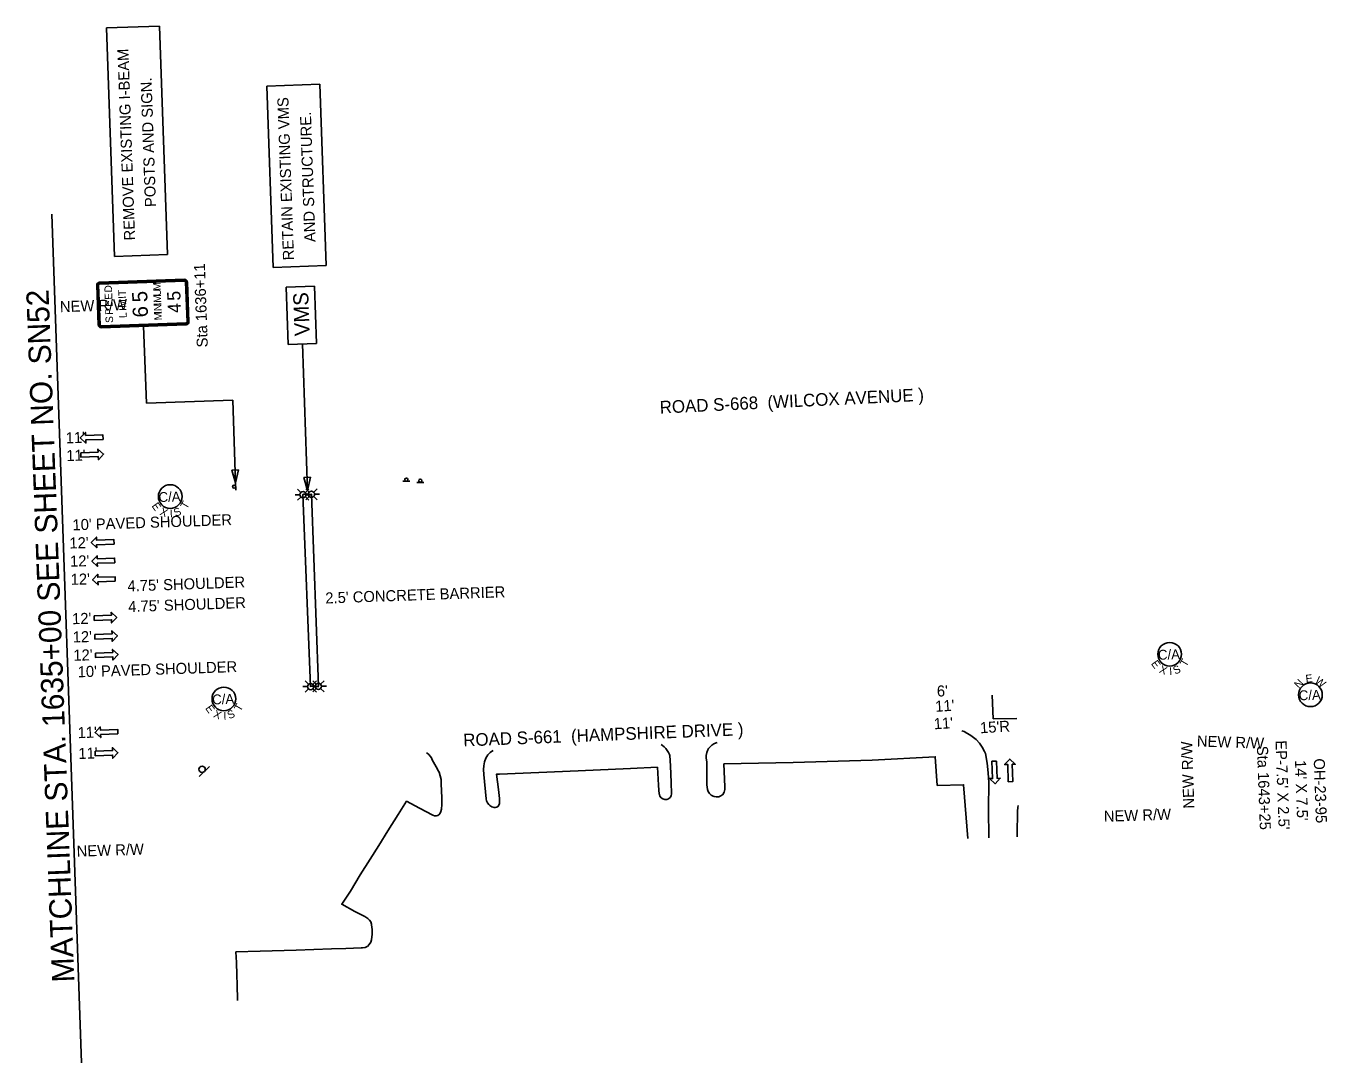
# Model space of a CAD drawing. Extents: x 1810445 to 1812085, y 1189733 to 1190648.
# Drawn here: x 1810445 to 1811270, y 1189817 to 1190475 of the extents above; entities that cross this region are included whole.
import ezdxf

# ---------------------------------------------------------------- set-up
doc = ezdxf.new("R2010")
doc.units = 0
for name, color, linetype in [('RD_EX_Misc', 7, 'Continuous'), ('RD_EX_Road', 7, 'Continuous'), ('RD_EX_UT', 7, 'Continuous'), ('RD_PD_Final_LnLine', 7, 'Continuous'), ('RD_PD_Final_TX', 7, 'Continuous'), ('RD_PD_RW_TX', 7, 'Continuous'), ('RD_SHT_MatchLine', 7, 'Continuous'), ('RD_SHT_TX', 7, 'Continuous'), ('RD_Sketch10', 7, 'Continuous'), ('RD_Sketch8', 7, 'Continuous'), ('RD_TX_RoadID', 7, 'Continuous'), ('SN_P_Signs', 7, 'Continuous')]:
    doc.layers.add(name, color=color, linetype=linetype)

# ---------------------------------------------------------------- blocks, each defined once
blk = doc.blocks.new('SARRW2')
at = {"layer": 'RD_PD_Final_LnLine'}
blk.add_lwpolyline([(-12, 1.2), (-12, -1.2), (-2.83, -1.2), (-2.83, -2.83), (0, 0), (-2.83, 2.83), (-2.83, 1.2)], close=True, dxfattribs=at)

msp = doc.modelspace()

# ---------------------------------------------------------------- linework, layer by layer
at = {"layer": 'RD_EX_Misc'}
msp.add_lwpolyline([(1810630.31, 1190056.09), (1810625.32, 1190055.92), (1810620.5, 1190177.71), (1810625.98, 1190177.88), (1810630.31, 1190056.09)], dxfattribs=at)
at = {"layer": 'RD_EX_Road'}
for points in [[(1811041.97, 1189959.43), (1811039.33, 1189993.58), (1811022.7, 1189993.16), (1811021.41, 1190011.32), (1810981.35, 1190009.17), (1810931.36, 1190007.76), (1810887.46, 1190006.81), (1810888.06, 1189992.18), (1810888.03, 1189990.52), (1810887.6, 1189988.91), (1810886.82, 1189987.44), (1810886.77, 1189987.37), (1810885.54, 1189986.52), (1810884.13, 1189986.01), (1810882.63, 1189985.88), (1810881.16, 1189986.15), (1810880.65, 1189986.34), (1810879.35, 1189986.99), (1810878.27, 1189987.97), (1810877.48, 1189989.2), (1810877.06, 1189990.6), (1810877.05, 1189990.64), (1810876.69, 1189993.44), (1810876.57, 1189999.43), (1810876.59, 1190006.08), (1810876.54, 1190008.14), (1810876.19, 1190010.35), (1810876.2, 1190012.2), (1810876.51, 1190014.06), (1810877.2, 1190015.81), (1810877.62, 1190016.53), (1810878.64, 1190017.65), (1810879.8, 1190018.63), (1810881.08, 1190019.45), (1810882.45, 1190020.1), (1810883.07, 1190020.29)], [(1811038.3, 1190027.77), (1811039.65, 1190027.28), (1811041.53, 1190026.38), (1811043.33, 1190025.31), (1811044.85, 1190024.21), (1811047.24, 1190022.24), (1811049.36, 1190019.99), (1811051.18, 1190017.48), (1811052.66, 1190014.76), (1811053.21, 1190013.49), (1811054.3, 1190007.31), (1811055, 1190001.07), (1811055.3, 1189995.02), (1811055.25, 1189978), (1811055.29, 1189959.9)], [(1810698.93, 1190013.8), (1810699.22, 1190013.63), (1810700.27, 1190012.75), (1810701.19, 1190011.74), (1810701.95, 1190010.6), (1810702.54, 1190009.36), (1810705.05, 1190004.91), (1810706.52, 1190002.15), (1810706.8, 1190001.55), (1810707.63, 1189999.22), (1810708.08, 1189996.8), (1810708.16, 1189993.31), (1810708.35, 1189990.47), (1810708.52, 1189984.36), (1810708.49, 1189981.12), (1810708.42, 1189978.17), (1810708.04, 1189976.59), (1810707.3, 1189975.15), (1810707.09, 1189974.85), (1810706.16, 1189974.16), (1810705.05, 1189973.81), (1810703.9, 1189973.85), (1810702.9, 1189974.23), (1810694.4, 1189978.82), (1810686.21, 1189983.15), (1810680.86, 1189974.72), (1810674.44, 1189964.28), (1810668.58, 1189955.14), (1810663.1, 1189946.34), (1810656.87, 1189936.47), (1810650.75, 1189926.07), (1810645.13, 1189917.74), (1810653.54, 1189913.25), (1810659.69, 1189909.93), (1810661.58, 1189908.72), (1810662.69, 1189907.77), (1810663.5, 1189906.56), (1810663.96, 1189905.17), (1810664.02, 1189904.82), (1810664.41, 1189901.68), (1810664.42, 1189898.51), (1810664.03, 1189895.36), (1810664.01, 1189895.3), (1810663.48, 1189893.69), (1810662.6, 1189892.25), (1810661.4, 1189891.05), (1810661.31, 1189890.98), (1810659.9, 1189890.35), (1810658.38, 1189890.1), (1810657.51, 1189890.13), (1810647.81, 1189889.77), (1810638.63, 1189889.42), (1810616.26, 1189888.58), (1810593.41, 1189887.93), (1810578.07, 1189887.51), (1810578.47, 1189880.93), (1810578.54, 1189872.9), (1810578.78, 1189866.75), (1810579.13, 1189857.1), (1810579.15, 1189856.63)], [(1810845.42, 1190004.73), (1810828.28, 1190003.91), (1810794.99, 1190002.48), (1810745.05, 1190000.29), (1810743.22, 1190000.2), (1810744.45, 1189990.48), (1810745.09, 1189984.93), (1810745.25, 1189982.83), (1810745.2, 1189981.65), (1810744.77, 1189980.54), (1810744.31, 1189979.93), (1810743.46, 1189979.34), (1810742.45, 1189979.1), (1810741.72, 1189979.17), (1810740.29, 1189979.66), (1810739.03, 1189980.5), (1810738.4, 1189981.14), (1810737.51, 1189982.19), (1810736.94, 1189983.46), (1810736.76, 1189984.55), (1810735.32, 1190000.01), (1810735.1, 1190003.19), (1810735.19, 1190005.64), (1810735.67, 1190008.05), (1810736.53, 1190010.35), (1810737.75, 1190012.49), (1810737.99, 1190012.84), (1810739.21, 1190014.12), (1810740.68, 1190015.1), (1810741.18, 1190015.29)], [(1810847.56, 1190019.04), (1810848.4, 1190018.56), (1810849.58, 1190017.65), (1810850.63, 1190016.59), (1810851.53, 1190015.4), (1810852.27, 1190014.1), (1810852.84, 1190012.72), (1810853.03, 1190012.06), (1810853.48, 1190005.56), (1810854, 1189995.09), (1810854.28, 1189987.73), (1810853.96, 1189986.53), (1810853.28, 1189985.49), (1810852.31, 1189984.71), (1810851.14, 1189984.28), (1810849.9, 1189984.22), (1810848.7, 1189984.56), (1810847.67, 1189985.25), (1810846.9, 1189986.23), (1810846.48, 1189987.4), (1810846.42, 1189987.79), (1810846.23, 1189990.06), (1810845.96, 1189993.27), (1810845.42, 1190004.73)], [(1811074.05, 1189980.37), (1811073.74, 1189979.19), (1811073.52, 1189976.75), (1811073.54, 1189975.74), (1811073.41, 1189963.08), (1811073.41, 1189960.54)]]:
    msp.add_lwpolyline(points, dxfattribs=at)
at = {"layer": 'RD_EX_UT'}
for p, q in [((1810618.63, 1190177.55), (1810615.7, 1190177.55)), ((1810617.17, 1190181.09), (1810619.26, 1190178.99)), ((1810623.92, 1190177.82), (1810620.99, 1190177.82)), ((1810622.08, 1190178.92), (1810624.24, 1190181.09)), ((1810622.46, 1190181.36), (1810624.55, 1190179.26)), ((1810622.46, 1190174.28), (1810624.54, 1190176.36)), ((1810625.7, 1190177.55), (1810622.63, 1190177.55)), ((1810627.37, 1190179.19), (1810629.53, 1190181.36)), ((1810627.38, 1190176.43), (1810629.53, 1190174.28)), ((1810630.99, 1190177.82), (1810627.92, 1190177.82)), ((1810617.17, 1190174.02), (1810619.25, 1190176.09)), ((1810622.09, 1190176.16), (1810624.24, 1190174.02)), ((1810623.45, 1190055.87), (1810620.52, 1190055.87)), ((1810621.98, 1190059.4), (1810624.08, 1190057.31)), ((1810621.98, 1190052.33), (1810624.06, 1190054.41)), ((1810628.3, 1190056.03), (1810625.37, 1190056.03)), ((1810626.83, 1190059.57), (1810628.93, 1190057.48)), ((1810626.83, 1190052.5), (1810628.91, 1190054.58)), ((1810626.89, 1190057.24), (1810629.05, 1190059.4)), ((1810626.9, 1190054.48), (1810629.05, 1190052.33)), ((1810630.52, 1190055.87), (1810627.45, 1190055.87)), ((1810631.74, 1190057.41), (1810633.9, 1190059.57)), ((1810631.76, 1190054.65), (1810633.9, 1190052.5)), ((1810635.37, 1190056.03), (1810632.3, 1190056.03))]:
    msp.add_line(p, q, dxfattribs=at)
for centre in [(1810620.63, 1190177.54), (1810625.92, 1190177.8), (1810625.45, 1190055.85), (1810630.3, 1190056.02)]:
    msp.add_circle(centre, 2, dxfattribs=at)
at = {"layer": 'RD_PD_Final_TX'}
for p in [(1811057.56, 1190050.46), (1811073.09, 1190035.56)]:
    msp.add_line(p, (1811058.09, 1190035.47), dxfattribs=at)
at = {"layer": 'RD_SHT_MatchLine'}
msp.add_line((1810461.25, 1190355.41), (1810480.22, 1189817.08), dxfattribs=at)
msp.add_line((1810461.25, 1190355.41), (1810480.22, 1189817.08), dxfattribs=at)
at = {"layer": 'RD_Sketch10'}
msp.add_circle((1811259.28, 1190050.64), 7.5, dxfattribs=at)
at = {"layer": 'RD_Sketch8'}
for centre in [(1810536.41, 1190176.38), (1811170.01, 1190076.35), (1810570.41, 1190048.02)]:
    msp.add_circle(centre, 7.5, dxfattribs=at)
at = {"layer": 'SN_P_Signs'}
for p, q in [((1810496.05, 1190473.67), (1810529.65, 1190474.86)), ((1810501.16, 1190328.74), (1810496.05, 1190473.67)), ((1810529.65, 1190474.86), (1810534.76, 1190329.93)), ((1810597.65, 1190436.71), (1810631.25, 1190437.89)), ((1810601.7, 1190321.76), (1810597.65, 1190436.71)), ((1810631.25, 1190437.89), (1810635.3, 1190322.95)), ((1810534.76, 1190329.93), (1810501.16, 1190328.74)), ((1810635.3, 1190322.95), (1810601.7, 1190321.76)), ((1810490.7, 1190285.23), (1810489.81, 1190310.42)), ((1810491.54, 1190312.28), (1810545.51, 1190314.18)), ((1810547.37, 1190312.45), (1810548.26, 1190287.26)), ((1810609.95, 1190309.28), (1810627.94, 1190309.92)), ((1810611.24, 1190272.9), (1810609.95, 1190309.28)), ((1810627.94, 1190309.92), (1810629.23, 1190273.54)), ((1810546.52, 1190285.4), (1810492.56, 1190283.5)), ((1810519.54, 1190284.45), (1810521.26, 1190235.61)), ((1810629.23, 1190273.54), (1810611.24, 1190272.9)), ((1810620.23, 1190273.22), (1810623.51, 1190180.31)), ((1810576.03, 1190237.54), (1810521.26, 1190235.61)), ((1810576.03, 1190237.54), (1810577.88, 1190184.98)), ((1810578.04, 1190180.49), (1810577.88, 1190184.98)), ((1810683.85, 1190186.14), (1810688.35, 1190186.14)), ((1810692.67, 1190185.4), (1810697.17, 1190185.4)), ((1810554.85, 1189998.73), (1810561.22, 1190005.1))]:
    msp.add_line(p, q, dxfattribs=at)
for points in [[(1810491.15, 1190285.25), (1810490.26, 1190310.43)], [(1810491.89, 1190285.28), (1810491.01, 1190310.46)], [(1810491.56, 1190311.83), (1810545.53, 1190313.73)], [(1810491.59, 1190311.08), (1810545.55, 1190312.98)], [(1810546.17, 1190312.4), (1810547.06, 1190287.22)], [(1810546.92, 1190312.43), (1810547.81, 1190287.25)], [(1810546.48, 1190286.6), (1810492.52, 1190284.7)], [(1810546.51, 1190285.85), (1810492.54, 1190283.95)]]:
    msp.add_lwpolyline(points, dxfattribs=at)
for points in [[(1810579.64, 1190193.25), (1810577.88, 1190184.98), (1810575.54, 1190193.11)], [(1810625.27, 1190188.58), (1810623.51, 1190180.31), (1810621.17, 1190188.43)]]:
    msp.add_lwpolyline(points, close=True, dxfattribs=at)
for centre, radius in [((1810686.11, 1190187.15), 1), ((1810694.93, 1190186.42), 1), ((1810576.95, 1190182.71), 1), ((1810556.61, 1190003.36), 2)]:
    msp.add_circle(centre, radius, dxfattribs=at)
for centre, radius, start, end in [((1810491.61, 1190310.48), 1.8, 92.01838, 182.01838), ((1810491.61, 1190310.48), 1.35, 92.01838, 182.01838), ((1810491.61, 1190310.48), 0.6, 92.01838, 182.01838), ((1810545.57, 1190312.38), 1.8, 2.01838, 92.01838), ((1810545.57, 1190312.38), 1.35, 2.01838, 92.01838), ((1810545.57, 1190312.38), 0.6, 2.01838, 92.01838), ((1810492.49, 1190285.3), 1.8, 182.01838, 272.01838), ((1810492.49, 1190285.3), 1.35, 182.01838, 272.01838), ((1810492.49, 1190285.3), 0.6, 182.01838, 272.01838), ((1810546.46, 1190287.2), 0.6, 272.01838, 2.01838), ((1810546.46, 1190287.2), 1.35, 272.01838, 2.01838), ((1810546.46, 1190287.2), 1.8, 272.01838, 2.01838)]:
    msp.add_arc(centre, radius, start, end, dxfattribs=at)

# ---------------------------------------------------------------- block references
at = {"layer": 'RD_PD_Final_LnLine', "xscale": 1.1999999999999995, "yscale": 1.2000000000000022}
for p, rotation in [((1810479.4, 1190213.58), -177.9816202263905), ((1810494.1, 1190203.27), 2.018379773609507), ((1810486.32, 1190147.15), -177.9816202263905), ((1810486.74, 1190135.37), -177.9816202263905), ((1810487.15, 1190123.59), -177.9816202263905), ((1810502.54, 1190099.75), 2.018379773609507), ((1810502.95, 1190087.97), 2.018379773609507), ((1810503.37, 1190076.19), 2.018379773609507), ((1810488.79, 1190026.72), -177.9816202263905), ((1810503.25, 1190013.92), 2.018379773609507), ((1811059.32, 1189994.19), -87.98162022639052), ((1811068.64, 1190009.9), 92.01837977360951)]:
    msp.add_blockref('SARRW2', p, dxfattribs=dict(at, rotation=rotation))

# ---------------------------------------------------------------- texts
at = {"layer": 'RD_PD_Final_TX'}
for s, rotation, p in [("11'", 2.01838, (1810470.24, 1190210.07)), ("11'", 2.01838, (1810470.64, 1190198.82)), ("10' PAVED SHOULDER", 1.90447, (1810474.55, 1190154.91)), ("12'", 1.39156, (1810472.57, 1190143.4)), ("12'", 1.39156, (1810472.98, 1190131.88)), ("12'", 1.39156, (1810473.38, 1190120.36)), ("4.75' SHOULDER", 2.01838, (1810509.41, 1190116.13)), ("2.5' CONCRETE BARRIER", 2.02012, (1810634.84, 1190108.51)), ("4.75' SHOULDER", 2.01838, (1810509.87, 1190103.07)), ("12'", 1.39156, (1810474.26, 1190095.39)), ("12'", 1.39156, (1810474.67, 1190083.8)), ("12'", 1.39156, (1810475.08, 1190072.21)), ("10' PAVED SHOULDER", 1.90447, (1810477.84, 1190061.7)), ("6'", 2.01838, (1811022.54, 1190049.46)), ("11'", 3.49537, (1811021.57, 1190039.8)), ("11'", 3.60734, (1811020.68, 1190028.72)), ("11'", 2.01838, (1810477.82, 1190023.08)), ("15'R ", 3.49537, (1811050.01, 1190026.2)), ("11'", 2.01838, (1810478.29, 1190009.88))]:
    msp.add_text(s, height=7, rotation=rotation, dxfattribs=at).set_placement(p)
at = {"layer": 'RD_PD_RW_TX'}
for rotation, p in [(1.89429, (1810466.57, 1190293.3)), (92.01838, (1811185.72, 1189978.59)), (358.10232, (1811187.16, 1190017.85)), (1.89429, (1811128.39, 1189970.04)), (1.89429, (1810477.19, 1189947.9))]:
    msp.add_text('NEW R/W', height=7, rotation=rotation, dxfattribs=at).set_placement(p)
at = {"layer": 'RD_SHT_TX'}
msp.add_text('MATCHLINE STA. 1635+00 SEE SHEET NO. SN52', height=14.1726, rotation=92.14236, dxfattribs=at).set_placement((1810475.67, 1189868.46))
at = {"layer": 'RD_Sketch10'}
for s, height, rotation, p in [('E', 5, 6.35143, (1811256.44, 1190058.25)), ('W', 5, 321.321, (1811261.62, 1190058.68)), ('N', 5, 46.88815, (1811252.02, 1190054.22)), ('C/A', 6.25, 2.01838, (1811251.98, 1190047.1))]:
    msp.add_text(s, height=height, rotation=rotation, dxfattribs=at).set_placement(p)
at = {"layer": 'RD_Sketch8'}
for s, height, rotation, p in [('C/A', 6.25, 2.01838, (1810529.11, 1190172.85)), ('E', 5, 305.22962, (1810524.39, 1190170.44)), ('X', 5, 337.659, (1810529.36, 1190164.95)), ('I', 5, 1.819, (1810536.22, 1190163.12)), ('S', 5, 23.81082, (1810539.86, 1190163.42)), ('T', 5, 60.20353, (1810546.9, 1190168.04)), ('C/A', 6.25, 2.01838, (1811162.71, 1190072.81)), ('E', 5, 305.22962, (1811157.99, 1190070.4)), ('X', 5, 337.659, (1811162.96, 1190064.91)), ('S', 5, 23.81082, (1811173.46, 1190063.39)), ('T', 5, 60.20353, (1811180.5, 1190068)), ('I', 5, 1.819, (1811169.81, 1190063.08)), ('E', 5, 305.22962, (1810558.39, 1190042.07)), ('C/A', 6.25, 2.01838, (1810563.12, 1190044.48)), ('T', 5, 60.20353, (1810580.9, 1190039.67)), ('X', 5, 337.659, (1810563.37, 1190036.59)), ('I', 5, 1.819, (1810570.22, 1190034.76)), ('S', 5, 23.81082, (1810573.86, 1190035.06))]:
    msp.add_text(s, height=height, rotation=rotation, dxfattribs=at).set_placement(p)
at = {"layer": 'RD_TX_RoadID'}
for s, rotation, p in [('ROAD S-668  (WILCOX AVENUE )', 2.77926, (1810846.93, 1190228.98)), ('ROAD S-661  (HAMPSHIRE DRIVE )', 2.29375, (1810722.34, 1190017.85))]:
    msp.add_text(s, height=8, rotation=rotation, dxfattribs=at).set_placement(p)
at = {"layer": 'SN_P_Signs'}
for s, height, rotation, p in [('REMOVE EXISTING I-BEAM', 6.9998, 92.01846, (1810514.17, 1190338.95)), ('POSTS AND SIGN.', 6.9998, 92.01846, (1810527.43, 1190360.14)), ('RETAIN EXISTING VMS', 6.9998, 92.01846, (1810614.91, 1190326.37)), ('AND STRUCTURE.', 6.9998, 92.01846, (1810628.51, 1190337.9)), ('Sta 1636+11', 7, 92.01846, (1810560.26, 1190271.12)), ('D', 4.8, 92.01838, (1810499.57, 1190305.89)), ('M', 4.8, 92.01838, (1810530.45, 1190307.13)), ('E', 4.8, 92.01838, (1810499.73, 1190301.35)), ('E', 4.8, 92.01838, (1810499.89, 1190296.81)), ('T', 4.8, 92.01838, (1810508.36, 1190303.73)), ('I', 4.8, 92.01838, (1810508.42, 1190301.92)), ('M', 4.8, 92.01838, (1810508.62, 1190296.26)), ('5', 9.6, 92.01838, (1810522, 1190299.78)), ('U', 4.8, 92.01838, (1810530.58, 1190303.5)), ('M', 4.8, 92.01838, (1810530.72, 1190299.38)), ('5', 8.4, 92.01838, (1810542.98, 1190300.73)), ('VMS', 9.6, 92.01838, (1810624.85, 1190278.33)), ('P', 4.8, 92.01838, (1810500.07, 1190291.71)), ('I', 4.8, 92.01838, (1810508.69, 1190294.2)), ('L', 4.8, 92.01838, (1810508.85, 1190289.69)), ('6', 9.6, 92.01838, (1810522.34, 1190290.16)), ('I', 4.8, 92.01838, (1810530.78, 1190297.7)), ('N', 4.8, 92.01838, (1810530.91, 1190294.06)), ('I', 4.8, 92.01838, (1810530.97, 1190292.38)), ('M', 4.8, 92.01838, (1810531.11, 1190288.26)), ('4', 8.4, 92.01838, (1810543.25, 1190293)), ('S', 4.8, 92.01838, (1810500.25, 1190286.61)), ("EP-7.5' X 2.5'", 7, 272.01846, (1811237.11, 1190021.62)), ('Sta 1643+25', 7, 272.01846, (1811225.33, 1190018.17)), ("14' X 7.5'", 7, 272.01846, (1811249.46, 1190009.04)), ('OH-23-95', 7, 272.01846, (1811261.33, 1190010.17))]:
    msp.add_text(s, height=height, rotation=rotation, dxfattribs=at).set_placement(p)

doc.saveas('drawing.dxf')
